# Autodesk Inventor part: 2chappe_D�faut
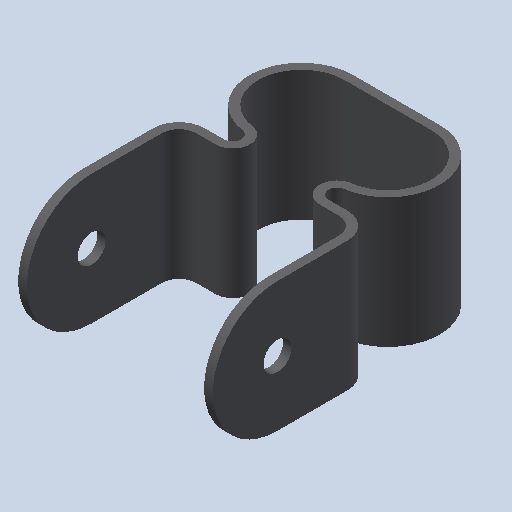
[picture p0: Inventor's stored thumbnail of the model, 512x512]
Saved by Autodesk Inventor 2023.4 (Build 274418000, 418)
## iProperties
Created: 2011-01
Part Number: 2chappe_D�faut
Document SubType Name: Modeling
Designer: eric
Density: 1 g/cm^3
Mass: 10.9274 g
Surface Area: 118.408 cm^2
Volume: 10.9274 cm^3
Material: Générique
Appearance: Green
Author: eric
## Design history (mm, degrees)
feature "Base1"
node "Corps solides"
node "Corps surfaciques"
node "Solide1"
